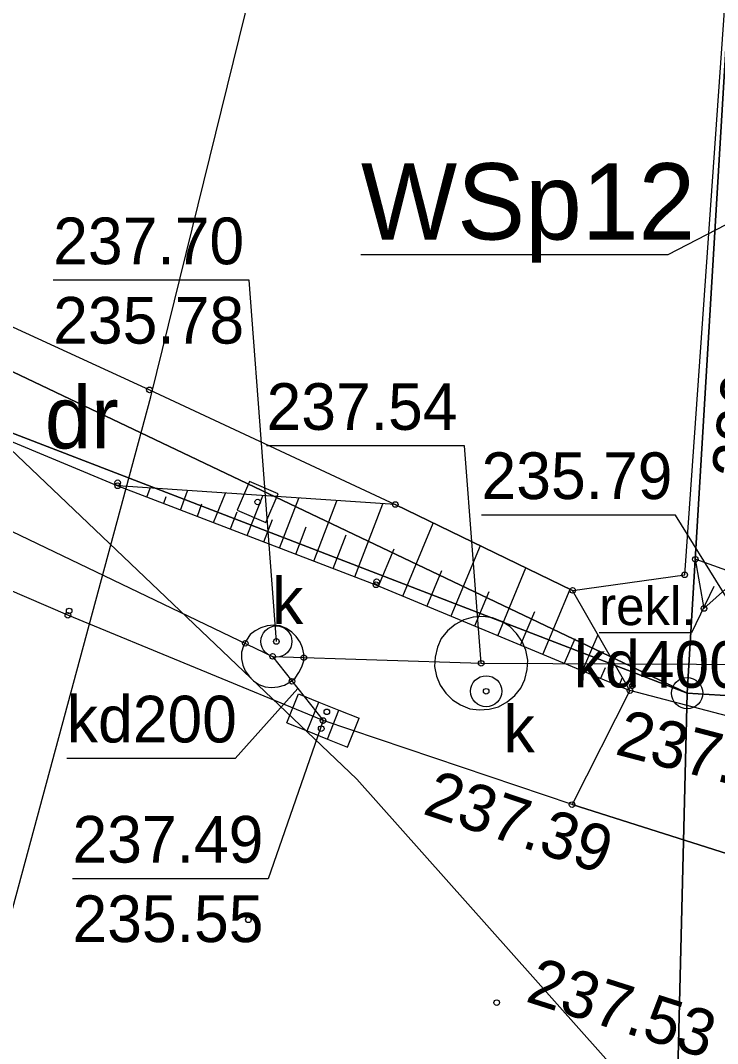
# Model space of a CAD drawing. Extents: x 6596400 to 6597200, y 5539751 to 5540251.
# Drawn here: x 6596703.94 to 6596715.14, y 5540094.36 to 5540110.79 of the extents above; entities that cross this region are included whole.
import ezdxf

# ---------------------------------------------------------------- set-up
doc = ezdxf.new("R2010")
doc.units = 0
for name, color, linetype in [('000 Inne (niezydentyfikowane)', 7, 'Continuous'), ('140-Punkty robocze', 7, 'Continuous'), ('202-punkt graniczny', 7, 'Continuous'), ('206-Nazwa miasta powiatu', 7, 'Continuous'), ('210-oznaczenie konturu użytku gruntowego', 7, 'Continuous'), ('218-kontur użytku gruntowego', 7, 'Continuous'), ('219-działka ewidencyjna', 7, 'Continuous'), ('chodnik', 7, 'Continuous'), ('inny obiekt zagospodarowania terenu', 7, 'Continuous'), ('jezdnia', 7, 'Continuous'), ('komora podziemna', 7, 'Continuous'), ('kratka ściekowa', 7, 'Continuous'), ('krawężnik', 7, 'Continuous'), ('Linia obszaru zagospodarowania terenu', 7, 'Continuous'), ('obszar utwardzony', 7, 'Continuous'), ('ogrodzenie trwałe', 7, 'Continuous'), ('Opis obszaru zagospodarowania terenu', 7, 'Continuous'), ('pikieta sztuczna', 7, 'Continuous'), ('pikieta sztuczna-Atr2', 7, 'Continuous'), ('przewód kanalizacyjny', 7, 'Continuous'), ('przewód kanalizacyjny-Atr1', 7, 'Continuous'), ('rzedna', 7, 'Continuous'), ('rzedna-Atr2', 7, 'Continuous'), ('rzedna-Atr3', 7, 'Continuous'), ('skarpa nieumocniona', 7, 'Continuous'), ('Strefa korytarza ekologicznego', 7, 'Continuous'), ('właz do komory lub kanału - kwadratowy', 7, 'Continuous'), ('właz do komory lub kanału - okrągły', 7, 'Continuous'), ('właz do komory lub kanału - okrągły-Atr17', 7, 'Continuous')]:
    doc.layers.add(name, color=color, linetype=linetype)

# ---------------------------------------------------------------- blocks, each defined once
blk = doc.blocks.new('202')
blk.add_circle((0, 0), 0.25)
blk = doc.blocks.new('US05')
for p, q in [((-0.525, -0.25), (-0.525, 0.25)), ((-0.525, 0.25), (-0.175, 0.25)), ((-0.175, -0.25), (-0.175, 0.25)), ((-0.175, 0.25), (0.175, 0.25)), ((0.175, -0.25), (0.175, 0.25)), ((0.175, 0.25), (0.525, 0.25)), ((0.525, -0.25), (0.525, 0.25)), ((-0.525, -0.25), (-0.175, -0.25)), ((-0.175, -0.25), (0.175, -0.25)), ((0.175, -0.25), (0.525, -0.25))]:
    blk.add_line(p, q)
blk = doc.blocks.new('US22')
blk.add_circle((0, 0), 0.25)
blk = doc.blocks.new('PW01')
blk.add_circle((0, 0), 0.045)
blk = doc.blocks.new('US22A')
blk.add_lwpolyline([(-0.25, -0.25), (0.25, -0.25), (0.25, 0.25), (-0.25, 0.25)], close=True)
blk = doc.blocks.new('PIKIETA')
blk.add_circle((0, 0), 0.045)

msp = doc.modelspace()

# ---------------------------------------------------------------- linework, layer by layer
at = {"layer": '000 Inne (niezydentyfikowane)'}
for points in [[(6596705.97, 5540103.14), (6596706.02, 5540103.28)], [(6596706.24, 5540103.04), (6596706.28, 5540103.15)], [(6596706.51, 5540102.93), (6596706.62, 5540103.24)], [(6596707.04, 5540102.73), (6596707.23, 5540103.2)], [(6596707.58, 5540102.52), (6596707.83, 5540103.16)], [(6596708.1, 5540102.32), (6596708.41, 5540103.12)], [(6596706.78, 5540102.83), (6596706.85, 5540103.03)], [(6596708.65, 5540102.11), (6596709.02, 5540103.08)], [(6596709.31, 5540101.86), (6596709.76, 5540103.03)], [(6596707.31, 5540102.63), (6596707.42, 5540102.9)], [(6596707.85, 5540102.42), (6596707.99, 5540102.78)], [(6596708.36, 5540102.22), (6596708.53, 5540102.66)], [(6596710.08, 5540101.55), (6596710.57, 5540102.72)], [(6596708.96, 5540101.99), (6596709.17, 5540102.53)], [(6596709.69, 5540101.71), (6596709.94, 5540102.31)], [(6596710.86, 5540101.23), (6596711.33, 5540102.36)], [(6596711.61, 5540100.91), (6596712.06, 5540102)], [(6596710.47, 5540101.39), (6596710.71, 5540101.96)], [(6596712.33, 5540100.61), (6596712.77, 5540101.66)], [(6596711.24, 5540101.07), (6596711.47, 5540101.62)], [(6596711.97, 5540100.76), (6596712.2, 5540101.3)], [(6596712.68, 5540100.47), (6596712.85, 5540100.87)], [(6596712.97, 5540100.35), (6596713.22, 5540100.93)], [(6596713.26, 5540100.22), (6596713.34, 5540100.4)], [(6596713.55, 5540100.1), (6596713.61, 5540100.24)]]:
    msp.add_lwpolyline(points, dxfattribs=at)
at = {"layer": '206-Nazwa miasta powiatu'}
msp.add_lwpolyline([(6596715.08, 5540101.7), (6596714.72, 5540100.96), (6596713.235, 5540100.96)], dxfattribs=at)
at = {"layer": '218-kontur użytku gruntowego'}
for points in [[(6596714.65, 5540099.99), (6596715.907, 5540120.962)], [(6596715.907, 5540120.962), (6596714.65, 5540099.99)], [(6596714.65, 5540099.99), (6596686.48, 5540113.41)], [(6596686.48, 5540113.41), (6596714.65, 5540099.99)], [(6596696.79, 5540106.87), (6596714.65, 5540099.99)], [(6596714.65, 5540099.99), (6596696.79, 5540106.87)], [(6596714.65, 5540099.99), (6596714.47, 5540092.63)], [(6596714.47, 5540092.63), (6596714.65, 5540099.99)], [(6596719.42, 5540099.7), (6596714.65, 5540099.99)], [(6596714.65, 5540099.99), (6596719.42, 5540099.7)]]:
    msp.add_lwpolyline(points, dxfattribs=at)
at = {"layer": '219-działka ewidencyjna'}
for points in [[(6596714.65, 5540099.99), (6596715.907, 5540120.962)], [(6596714.65, 5540099.99), (6596696.79, 5540106.87)], [(6596714.47, 5540092.63), (6596714.65, 5540099.99)], [(6596714.65, 5540099.99), (6596719.42, 5540099.7)]]:
    msp.add_lwpolyline(points, dxfattribs=at)
at = {"layer": 'chodnik'}
msp.add_lwpolyline([(6596672.08, 5540122.71), (6596677.31, 5540119.95), (6596676.14, 5540117.82), (6596682.08, 5540114.47), (6596682.62, 5540115.47), (6596686.44, 5540113.75), (6596685.85, 5540112.45), (6596693.18, 5540108.72), (6596693.76, 5540110.35), (6596698.55, 5540108.24), (6596697.87, 5540106.5), (6596705.5, 5540103.32), (6596709.65, 5540101.73), (6596713.73, 5540100.03), (6596712.8, 5540098.2), (6596708.8, 5540099.55), (6596704.7, 5540101.24), (6596694.34, 5540105.7), (6596683.34, 5540111.32), (6596679.35, 5540113.39), (6596672.62, 5540117.3)], dxfattribs=at)
at = {"layer": 'inny obiekt zagospodarowania terenu'}
msp.add_lwpolyline([(6596714.78, 5540102.14), (6596714.92, 5540101.35), (6596715.51, 5540101.88)], close=True, dxfattribs=at)
at = {"layer": 'jezdnia'}
msp.add_lwpolyline([(6596728.26, 5540094.5), (6596723.35, 5540095.14), (6596720.92, 5540095.72), (6596718.03, 5540096.54), (6596712.8, 5540098.2), (6596708.8, 5540099.55), (6596704.7, 5540101.24), (6596694.34, 5540105.7), (6596683.34, 5540111.32), (6596679.35, 5540113.39), (6596672.62, 5540117.3), (6596666.82, 5540120.65), (6596657.79, 5540125.88), (6596655.967, 5540126.802)], dxfattribs=at)
at = {"layer": 'komora podziemna'}
for points in [[(6596710.77, 5540099.99), (6596710.88, 5540099.88), (6596711.01, 5540099.8), (6596711.16, 5540099.74), (6596711.31, 5540099.72), (6596711.47, 5540099.73), (6596711.62, 5540099.77), (6596711.76, 5540099.85), (6596711.88, 5540099.95), (6596711.98, 5540100.07), (6596712.04, 5540100.21), (6596712.08, 5540100.37), (6596712.09, 5540100.52), (6596712.06, 5540100.68), (6596712, 5540100.82), (6596711.91, 5540100.95), (6596711.8, 5540101.06), (6596711.67, 5540101.14), (6596711.52, 5540101.2), (6596711.37, 5540101.22), (6596711.21, 5540101.21), (6596711.06, 5540101.17), (6596710.92, 5540101.09), (6596710.8, 5540100.99), (6596710.7, 5540100.87), (6596710.64, 5540100.73), (6596710.6, 5540100.57), (6596710.59, 5540100.42), (6596710.62, 5540100.26), (6596710.68, 5540100.12)], [(6596707.61, 5540100.26), (6596707.68, 5540100.19), (6596707.77, 5540100.13), (6596707.87, 5540100.09), (6596707.97, 5540100.08), (6596708.08, 5540100.09), (6596708.18, 5540100.12), (6596708.27, 5540100.17), (6596708.35, 5540100.23), (6596708.41, 5540100.32), (6596708.46, 5540100.41), (6596708.49, 5540100.51), (6596708.49, 5540100.62), (6596708.47, 5540100.72), (6596708.43, 5540100.81), (6596708.37, 5540100.9), (6596708.3, 5540100.97), (6596708.21, 5540101.03), (6596708.11, 5540101.07), (6596708.01, 5540101.08), (6596707.9, 5540101.07), (6596707.8, 5540101.04), (6596707.71, 5540100.99), (6596707.63, 5540100.93), (6596707.57, 5540100.84), (6596707.52, 5540100.75), (6596707.49, 5540100.65), (6596707.49, 5540100.54), (6596707.51, 5540100.44), (6596707.55, 5540100.35)]]:
    msp.add_lwpolyline(points, close=True, dxfattribs=at)
at = {"layer": 'krawężnik'}
msp.add_lwpolyline([(6596712.8, 5540098.2), (6596708.8, 5540099.55), (6596704.7, 5540101.24), (6596694.34, 5540105.7), (6596683.34, 5540111.32), (6596679.35, 5540113.39), (6596672.62, 5540117.3), (6596666.82, 5540120.65), (6596657.79, 5540125.88), (6596655.967, 5540126.802)], dxfattribs=at)
at = {"layer": 'Linia obszaru zagospodarowania terenu'}
msp.add_lwpolyline([(6596664.616, 5540132.112), (6596671.21, 5540127.95), (6596681.8, 5540121.54), (6596690.35, 5540115.69), (6596701.61, 5540105.97), (6596709.34, 5540098.61), (6596715.39, 5540091.82), (6596718.63, 5540088.53), (6596721.87, 5540084.71), (6596726.1, 5540083.21), (6596730.7, 5540082.79), (6596730.91, 5540075), (6596745.51, 5540074.64), (6596746.77, 5540082.74), (6596765.15, 5540085.09), (6596776.62, 5540086.27), (6596789.34, 5540086.1), (6596798.37, 5540085.54), (6596805.65, 5540083.56), (6596813.11, 5540081.53), (6596819.41, 5540077.54), (6596826.58, 5540072.81), (6596832.721, 5540067.998)], dxfattribs=at)
at = {"layer": 'obszar utwardzony'}
msp.add_lwpolyline([(6596713.73, 5540100.03), (6596712.8, 5540098.2), (6596718.03, 5540096.54), (6596719.7, 5540098.47)], close=True, dxfattribs=at)
at = {"layer": 'ogrodzenie trwałe'}
for points in [[(6596714.61, 5540101.89), (6596715.7, 5540117.35), (6596715.95, 5540120.963)], [(6596698.55, 5540108.24), (6596702.22, 5540106.6), (6596706.01, 5540104.86), (6596709.96, 5540103.02), (6596712.81, 5540101.64), (6596714.61, 5540101.89)]]:
    msp.add_lwpolyline(points, dxfattribs=at)
at = {"layer": 'Opis obszaru zagospodarowania terenu'}
msp.add_lwpolyline([(6596717.28, 5540108.55), (6596714.34, 5540107.03), (6596709.408, 5540107.03)], dxfattribs=at)
at = {"layer": 'przewód kanalizacyjny'}
for points in [[(6596652.409, 5540119.314), (6596659.51, 5540115.47), (6596667.73, 5540121.28), (6596680.3, 5540113.87), (6596707.99, 5540100.58), (6596711.34, 5540100.47), (6596715.95, 5540100.45)], [(6596707.99, 5540100.58), (6596708.8, 5540099.55)]]:
    msp.add_lwpolyline(points, dxfattribs=at)
at = {"layer": 'przewód kanalizacyjny-Atr1'}
msp.add_lwpolyline([(6596708.397, 5540100.063), (6596707.39, 5540098.94), (6596704.683, 5540098.94)], dxfattribs=at)
at = {"layer": 'rzedna-Atr2'}
for points in [[(6596708.05, 5540100.82), (6596707.61, 5540106.62), (6596704.464, 5540106.62)], [(6596711.34, 5540100.47), (6596711.07, 5540103.96), (6596707.892, 5540103.96)], [(6596715.95, 5540100.45), (6596714.46, 5540102.85), (6596711.346, 5540102.85)], [(6596708.8, 5540099.55), (6596707.92, 5540097.01), (6596704.774, 5540097.01)]]:
    msp.add_lwpolyline(points, dxfattribs=at)
at = {"layer": 'skarpa nieumocniona'}
msp.add_lwpolyline([(6596709.96, 5540103.02), (6596705.5, 5540103.32), (6596709.65, 5540101.73), (6596713.73, 5540100.03), (6596712.81, 5540101.64)], close=True, dxfattribs=at)
msp.add_lwpolyline([(6596709.96, 5540103.02), (6596705.5, 5540103.32), (6596709.65, 5540101.73), (6596713.73, 5540100.03), (6596712.81, 5540101.64)], close=True, dxfattribs=at)
at = {"layer": 'Strefa korytarza ekologicznego'}
msp.add_lwpolyline([(6596698.383, 5540076.46), (6596706.03, 5540104.75), (6596710.01, 5540120.89)], dxfattribs=at)

# ---------------------------------------------------------------- block references
at = {"layer": '140-Punkty robocze'}
for p in [(6596706.01, 5540104.86), (6596705.5, 5540103.37), (6596705.5, 5540103.32), (6596707.75, 5540103.06), (6596709.96, 5540103.02), (6596714.78, 5540102.14), (6596709.66, 5540101.78), (6596714.61, 5540101.89), (6596709.65, 5540101.73), (6596712.81, 5540101.64), (6596704.72, 5540101.31), (6596714.92, 5540101.35), (6596704.7, 5540101.24), (6596707.55, 5540100.79), (6596708.05, 5540100.82), (6596707.99, 5540100.58), (6596708.49, 5540100.56), (6596708.3, 5540100.18), (6596713.77, 5540100.11), (6596711.42, 5540100.02), (6596708.86, 5540099.69), (6596708.8, 5540099.55), (6596708.77, 5540099.42), (6596707.6, 5540096.35)]:
    msp.add_blockref('PIKIETA', p, dxfattribs=at)
at = {"layer": '202-punkt graniczny'}
msp.add_blockref('202', (6596714.65, 5540099.99), dxfattribs=at)
at = {"layer": 'kratka ściekowa', "rotation": -21.93000000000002}
msp.add_blockref('US05', (6596708.8, 5540099.55), dxfattribs=at)
at = {"layer": 'pikieta sztuczna'}
for p in [(6596713.73, 5540100.03), (6596712.8, 5540098.2), (6596711.59, 5540095.02)]:
    msp.add_blockref('PW01', p, dxfattribs=at)
at = {"layer": 'rzedna'}
for p in [(6596708.05, 5540100.82), (6596711.34, 5540100.47), (6596708.8, 5540099.55)]:
    msp.add_blockref('PW01', p, dxfattribs=at)
at = {"layer": 'właz do komory lub kanału - kwadratowy', "rotation": -22.989000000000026}
msp.add_blockref('US22A', (6596707.75, 5540103.06), dxfattribs=at)
at = {"layer": 'właz do komory lub kanału - okrągły'}
for p in [(6596708.05, 5540100.82), (6596711.42, 5540100.02)]:
    msp.add_blockref('US22', p, dxfattribs=at)

# ---------------------------------------------------------------- texts
at = {"layer": '206-Nazwa miasta powiatu'}
msp.add_text('rekl.', height=0.613, dxfattribs=at).set_placement((6596713.235, 5540101.082))
at = {"layer": '210-oznaczenie konturu użytku gruntowego'}
msp.add_text('dr', height=1, dxfattribs=at).set_placement((6596704.33, 5540103.92))
at = {"layer": 'Opis obszaru zagospodarowania terenu'}
msp.add_text('WSp12', height=1.225, dxfattribs=at).set_placement((6596709.408, 5540107.275))
at = {"layer": 'pikieta sztuczna-Atr2'}
for s, rotation, p in [('236.33', 84.011, (6596715.786, 5540103.412)), ('237.36', 345.356, (6596713.47, 5540099.014)), ('237.39', 341.35, (6596710.38, 5540098.059)), ('237.53', 342.391, (6596712.033, 5540095.045))]:
    msp.add_text(s, height=0.75, rotation=rotation, dxfattribs=at).set_placement(p)
at = {"layer": 'przewód kanalizacyjny-Atr1'}
msp.add_text('kd400', height=0.75, rotation=359.751, dxfattribs=at).set_placement((6596712.828, 5540100.085))
msp.add_text('kd200', height=0.75, dxfattribs=at).set_placement((6596704.683, 5540099.198))
at = {"layer": 'rzedna-Atr2'}
for s, p in [('237.70', (6596704.464, 5540106.878)), ('237.54', (6596707.892, 5540104.218)), ('235.79', (6596711.346, 5540103.107)), ('237.49', (6596704.774, 5540097.268))]:
    msp.add_text(s, height=0.75, dxfattribs=at).set_placement(p)
at = {"layer": 'rzedna-Atr3'}
for s, p in [('235.78', (6596704.464, 5540105.603)), ('235.55', (6596704.774, 5540095.992))]:
    msp.add_text(s, height=0.75, dxfattribs=at).set_placement(p)
at = {"layer": 'właz do komory lub kanału - okrągły-Atr17'}
for p in [(6596707.98, 5540101.1), (6596711.7, 5540099.04)]:
    msp.add_text('k', height=0.75, dxfattribs=at).set_placement(p)

doc.saveas('drawing.dxf')
